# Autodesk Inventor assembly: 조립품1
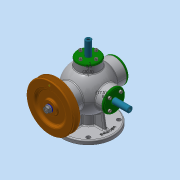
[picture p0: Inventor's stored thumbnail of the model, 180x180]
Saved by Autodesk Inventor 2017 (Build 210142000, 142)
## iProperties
Part Number: 조립품1
Material: 일반
Document SubType Name: Assembly
Designer: MRC
Mass: 3778.22 g
Surface Area: 2410.88 cm^2
Volume: 904.614 cm^3
Density: 4.17661 g/cm^3
Author: MRC
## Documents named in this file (17)
- C:\Users\MRC\Desktop\600911V1007\조립품1.iam
- C:\Users\MRC\Desktop\600911V1007\V-벨트풀리.ipt
- C:\Users\MRC\Desktop\600911V1007\너트 M8x1.ipt
- C:\Users\MRC\Desktop\600911V1007\뒤커버.ipt
- C:\Users\MRC\Desktop\600911V1007\베어링 6202.ipt
- C:\Users\MRC\Desktop\600911V1007\본체.ipt
- C:\Users\MRC\Desktop\600911V1007\본체커버.ipt
- C:\Users\MRC\Desktop\600911V1007\볼트 M4.ipt
- C:\Users\MRC\Desktop\600911V1007\스프링1.ipt
- C:\Users\MRC\Desktop\600911V1007\스프링2.ipt
- C:\Users\MRC\Desktop\600911V1007\슬라이드 커버.ipt
- C:\Users\MRC\Desktop\600911V1007\슬라이드.ipt
- C:\Users\MRC\Desktop\600911V1007\앞커버.ipt
- C:\Users\MRC\Desktop\600911V1007\오일 실.ipt
- C:\Users\MRC\Desktop\600911V1007\와셔 8x17.ipt
- C:\Users\MRC\Desktop\600911V1007\축.ipt
- C:\Users\MRC\Desktop\600911V1007\키 4x4.ipt
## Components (1 placed, 1 different names)
1. V-벨트풀리:1
